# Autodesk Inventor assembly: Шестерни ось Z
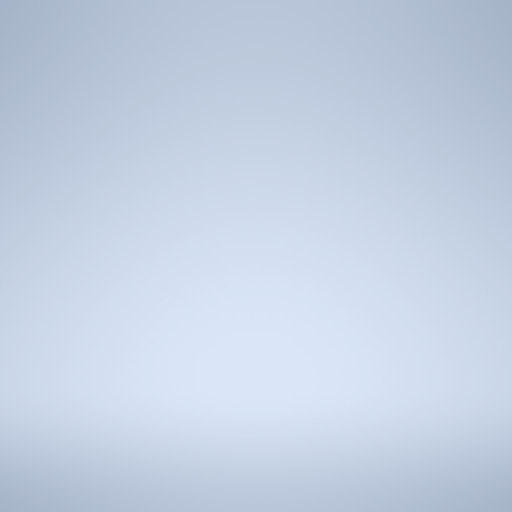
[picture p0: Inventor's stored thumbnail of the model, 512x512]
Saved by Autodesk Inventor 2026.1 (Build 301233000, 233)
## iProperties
Created: 2026-01
Part Number: Шестерни ось Z
Document SubType Name: Assembly
Designer: Yury Melnikov
Author: Yury Melnikov
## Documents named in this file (1)
- C:\Users\user\Documents\Проекты\ВсОШ_РОБО\Робот V2\Шестерни ось Z.iam
